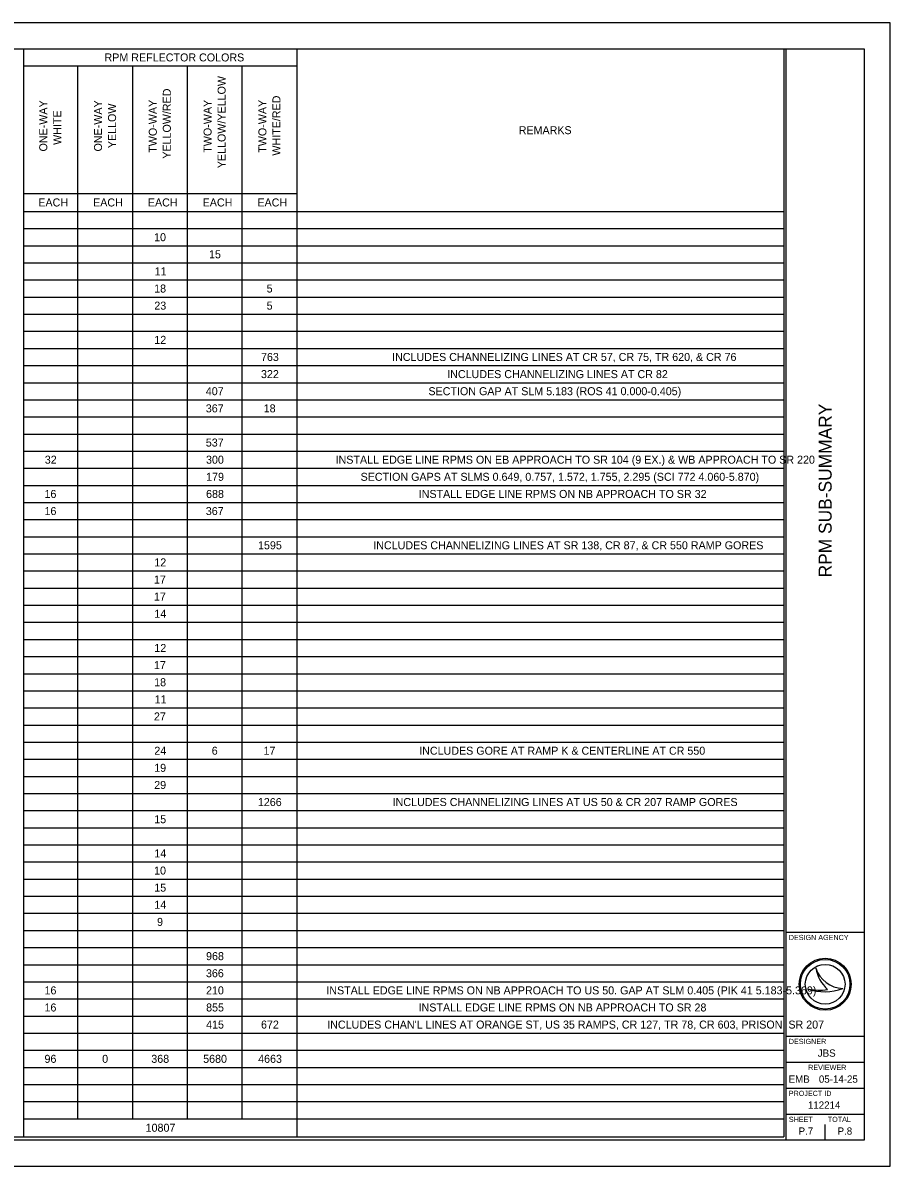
# Model space of a CAD drawing. Extents: x 0 to 34, y 0 to 22.
# Drawn here: x 17.31 to 34, y 0 to 22 of the extents above; entities that cross this region are included whole.
import ezdxf

# ---------------------------------------------------------------- set-up
doc = ezdxf.new("R2010")
doc.units = 0
for name, color, linetype in [('Default', 7, 'Continuous'), ('SH_Border', 7, 'Continuous'), ('SH_Cut_Line', 7, 'Continuous'), ('SH_Data', 7, 'Continuous')]:
    doc.layers.add(name, color=color, linetype=linetype)

msp = doc.modelspace()

# ---------------------------------------------------------------- linework, layer by layer
at = {"layer": 'Default'}
for p, q in [((15.193, 21.5), (17.323, 21.5)), ((17.301, 21.5), (31.954, 21.5)), ((17.323, 21.5), (17.323, 0.566)), ((22.582, 21.5), (22.582, 0.566)), ((31.954, 21.5), (31.954, 0.566)), ((17.323, 21.171), (22.582, 21.171)), ((18.366, 21.171), (18.366, 0.912)), ((19.42, 21.171), (19.42, 0.912)), ((20.474, 21.171), (20.474, 0.912)), ((21.528, 21.171), (21.528, 0.912)), ((17.323, 18.716), (22.582, 18.716)), ((17.323, 18.371), (31.954, 18.371)), ((17.323, 18.041), (31.954, 18.041)), ((17.323, 17.712), (31.954, 17.712)), ((17.323, 17.382), (31.954, 17.382)), ((17.323, 17.053), (31.954, 17.053)), ((17.323, 16.724), (31.954, 16.724)), ((17.323, 16.394), (31.954, 16.394)), ((17.323, 16.065), (31.954, 16.065)), ((17.323, 15.735), (31.954, 15.735)), ((17.323, 15.406), (31.954, 15.406)), ((17.323, 15.076), (31.954, 15.076)), ((17.323, 14.747), (31.954, 14.747)), ((17.323, 14.418), (31.954, 14.418)), ((17.323, 14.088), (31.954, 14.088)), ((17.323, 13.759), (31.954, 13.759)), ((17.323, 13.429), (31.954, 13.429)), ((17.323, 13.1), (31.954, 13.1)), ((17.323, 12.771), (31.954, 12.771)), ((17.323, 12.441), (31.954, 12.441)), ((17.323, 12.112), (31.954, 12.112)), ((17.323, 11.782), (31.954, 11.782)), ((17.323, 11.453), (31.954, 11.453)), ((17.323, 11.124), (31.954, 11.124)), ((17.323, 10.794), (31.954, 10.794)), ((17.323, 10.465), (31.954, 10.465)), ((17.323, 10.135), (31.954, 10.135)), ((17.323, 9.806), (31.954, 9.806)), ((17.323, 9.476), (31.954, 9.476)), ((17.323, 9.147), (31.954, 9.147)), ((17.323, 8.818), (31.954, 8.818)), ((17.323, 8.488), (31.954, 8.488)), ((17.323, 8.159), (31.954, 8.159)), ((17.323, 7.829), (31.954, 7.829)), ((17.323, 7.5), (31.954, 7.5)), ((17.323, 7.171), (31.954, 7.171)), ((17.323, 6.841), (31.954, 6.841)), ((17.323, 6.512), (31.954, 6.512)), ((17.323, 6.182), (31.954, 6.182)), ((17.323, 5.853), (31.954, 5.853)), ((17.323, 5.524), (31.954, 5.524)), ((17.323, 5.194), (31.954, 5.194)), ((17.323, 4.865), (31.954, 4.865)), ((17.323, 4.535), (31.954, 4.535)), ((17.323, 4.206), (31.954, 4.206)), ((17.323, 3.876), (31.954, 3.876)), ((17.323, 3.547), (31.954, 3.547)), ((17.323, 3.218), (31.954, 3.218)), ((17.323, 2.888), (31.954, 2.888)), ((17.323, 2.559), (31.954, 2.559)), ((17.323, 2.229), (31.954, 2.229)), ((17.323, 1.9), (31.954, 1.9)), ((17.323, 1.571), (31.954, 1.571)), ((17.323, 1.241), (31.954, 1.241)), ((17.323, 0.912), (31.954, 0.912)), ((15.193, 0.566), (17.323, 0.566)), ((17.301, 0.566), (31.954, 0.566))]:
    msp.add_line(p, q, dxfattribs=at)
at = {"layer": 'SH_Border'}
for p, q in [((32, 0.5), (32, 21.5)), ((32, 4.5), (33.5, 4.5)), ((32, 2.5), (33.5, 2.5)), ((32, 2), (33.5, 2)), ((32, 1.5), (33.5, 1.5)), ((32, 1), (33.5, 1))]:
    msp.add_line(p, q, dxfattribs=at)
msp.add_lwpolyline([(1.5, 21.5), (33.5, 21.5), (33.5, 0.5), (1.5, 0.5)], close=True, dxfattribs=at)
at = {"layer": 'SH_Cut_Line'}
msp.add_lwpolyline([(0, 0), (34, 0), (34, 22), (0, 22)], close=True, dxfattribs=at)
at = {"layer": 'SH_Data'}
for p, q in [((32.567, 3.81), (32.567, 3.81)), ((32.417, 3.41), (32.417, 3.41)), ((32.75, 3.5), (32.75, 3.5)), ((33.087, 3.419), (33.087, 3.419)), ((32.375, 0.675), (32.375, 0.675)), ((32.75, 0.5), (32.75, 0.8))]:
    msp.add_line(p, q, dxfattribs=at)
for radius in [0.5, 0.477, 0.477, 0.382]:
    msp.add_circle((32.75, 3.5), radius, dxfattribs=at)
for centre, radius, start, end in [((33.116, 3.998), 0.58, 198.9257, 198.9319), ((33.347, 3.97), 0.796, 191.6379, 191.6421), ((33.116, 3.998), 0.58, 198.9319, 267.1657), ((33.347, 3.97), 0.796, 191.6421, 226.0947), ((32.739, 4.37), 1.013, 251.4576, 290.0832), ((32.648, 4.654), 1.266, 259.4964, 259.4995), ((32.739, 4.37), 1.013, 251.4527, 251.4576), ((32.648, 4.654), 1.266, 259.4995, 276.6672)]:
    msp.add_arc(centre, radius, start, end, dxfattribs=at)

# ---------------------------------------------------------------- texts
at = {"layer": 'Default'}
for s, p in [('RPM REFLECTOR COLORS', (18.883, 21.258)), ('REMARKS', (26.853, 19.858)), ('EACH', (17.609, 18.467)), ('EACH', (18.663, 18.467)), ('EACH', (19.717, 18.467)), ('EACH', (20.771, 18.467)), ('EACH', (21.825, 18.467)), ('10', (19.837, 17.799)), ('15', (20.894, 17.47)), ('11', (19.847, 17.141)), ('18', (19.838, 16.811)), ('5', (22.003, 16.811)), ('23', (19.841, 16.482)), ('5', (22.003, 16.482)), ('12', (19.841, 15.823)), ('763', (21.894, 15.494)), ('INCLUDES CHANNELIZING LINES AT CR 57, CR 75, TR 620, & CR 76', (24.417, 15.494)), ('322', (21.894, 15.164)), ('INCLUDES CHANNELIZING LINES AT CR 82', (25.477, 15.164)), ('407', (20.832, 14.835)), ('SECTION GAP AT SLM 5.183 (ROS 41 0.000-0.405)', (25.116, 14.835)), ('367', (20.832, 14.505)), ('18', (21.946, 14.505)), ('537', (20.832, 13.847)), ('32', (17.733, 13.517)), ('300', (20.836, 13.517)), ('INSTALL EDGE LINE RPMS ON EB APPROACH TO SR 104 (9 EX.) & WB APPROACH TO SR 220', (23.329, 13.517)), ('179', (20.838, 13.188)), ('SECTION GAPS AT SLMS 0.649, 0.757, 1.572, 1.755, 2.295 (SCI 772 4.060-5.870)', (23.81, 13.188)), ('16', (17.728, 12.858)), ('688', (20.837, 12.858)), ('INSTALL EDGE LINE RPMS ON NB APPROACH TO SR 32', (24.929, 12.858)), ('16', (17.728, 12.529)), ('367', (20.832, 12.529)), ('1595', (21.837, 11.87)), ('INCLUDES CHANNELIZING LINES AT SR 138, CR 87, & CR 550 RAMP GORES', (24.054, 11.87)), ('12', (19.841, 11.541)), ('17', (19.834, 11.211)), ('17', (19.834, 10.882)), ('14', (19.841, 10.552)), ('12', (19.841, 9.894)), ('17', (19.834, 9.564)), ('18', (19.838, 9.235)), ('11', (19.847, 8.905)), ('27', (19.834, 8.576)), ('24', (19.841, 7.917)), ('6', (20.946, 7.917)), ('17', (21.942, 7.917)), ('INCLUDES GORE AT RAMP K & CENTERLINE AT CR 550', (24.938, 7.917)), ('19', (19.839, 7.588)), ('29', (19.839, 7.258)), ('1266', (21.834, 6.929)), ('INCLUDES CHANNELIZING LINES AT US 50 & CR 207 RAMP GORES', (24.427, 6.929)), ('15', (19.84, 6.599)), ('14', (19.841, 5.941)), ('10', (19.837, 5.611)), ('15', (19.84, 5.282)), ('14', (19.841, 4.952)), ('9', (19.894, 4.623)), ('968', (20.837, 3.964)), ('366', (20.835, 3.635)), ('16', (17.728, 3.305)), ('210', (20.836, 3.305)), ('INSTALL EDGE LINE RPMS ON NB APPROACH TO US 50. GAP AT SLM 0.405 (PIK 41 5.183-5.369)', (23.151, 3.305)), ('16', (17.728, 2.976)), ('855', (20.838, 2.976)), ('INSTALL EDGE LINE RPMS ON NB APPROACH TO SR 28', (24.926, 2.976)), ('415', (20.838, 2.647)), ('672', (21.894, 2.647)), ("INCLUDES CHAN'L LINES AT ORANGE ST, US 35 RAMPS, CR 127, TR 78, CR 603, PRISON, SR 207", (23.168, 2.647)), ('96', (17.728, 1.988)), ('0', (18.838, 1.988)), ('368', (19.783, 1.988)), ('5680', (20.781, 1.988)), ('4663', (21.839, 1.988)), ('10807', (19.674, 0.662))]:
    msp.add_text(s, height=0.154, dxfattribs=at).set_placement(p)
for s, p in [('YELLOW/YELLOW', (21.213, 19.203)), ('YELLOW/RED', (20.159, 19.386)), ('ONE-WAY ', (17.781, 19.525)), ('ONE-WAY', (18.835, 19.525)), ('TWO-WAY', (19.889, 19.501)), ('TWO-WAY', (20.943, 19.501)), ('TWO-WAY', (21.998, 19.501)), ('WHITE/RED', (22.267, 19.445)), ('WHITE', (18.051, 19.652)), ('YELLOW', (19.105, 19.589))]:
    msp.add_text(s, height=0.154, rotation=90, dxfattribs=at).set_placement(p)
at = {"layer": 'SH_Data'}
msp.add_text('RPM SUB-SUMMARY', height=0.25, rotation=90, dxfattribs=at).set_placement((32.875, 11.329))
for s, height, p in [('DESIGN AGENCY', 0.1, (32.05, 4.35)), ('DESIGNER', 0.1, (32.05, 2.35)), ('JBS', 0.14, (32.608, 2.105)), ('REVIEWER', 0.1, (32.422, 1.85)), ('EMB', 0.14, (32.047, 1.605)), ('05-14-25', 0.14, (32.629, 1.605)), ('PROJECT ID', 0.1, (32.05, 1.35)), ('112214', 0.14, (32.418, 1.105)), ('SHEET', 0.1, (32.05, 0.85)), ('TOTAL', 0.1, (32.8, 0.85)), ('P.7', 0.14, (32.239, 0.605)), ('P.8', 0.14, (32.989, 0.605))]:
    msp.add_text(s, height=height, dxfattribs=at).set_placement(p)

doc.saveas('drawing.dxf')
